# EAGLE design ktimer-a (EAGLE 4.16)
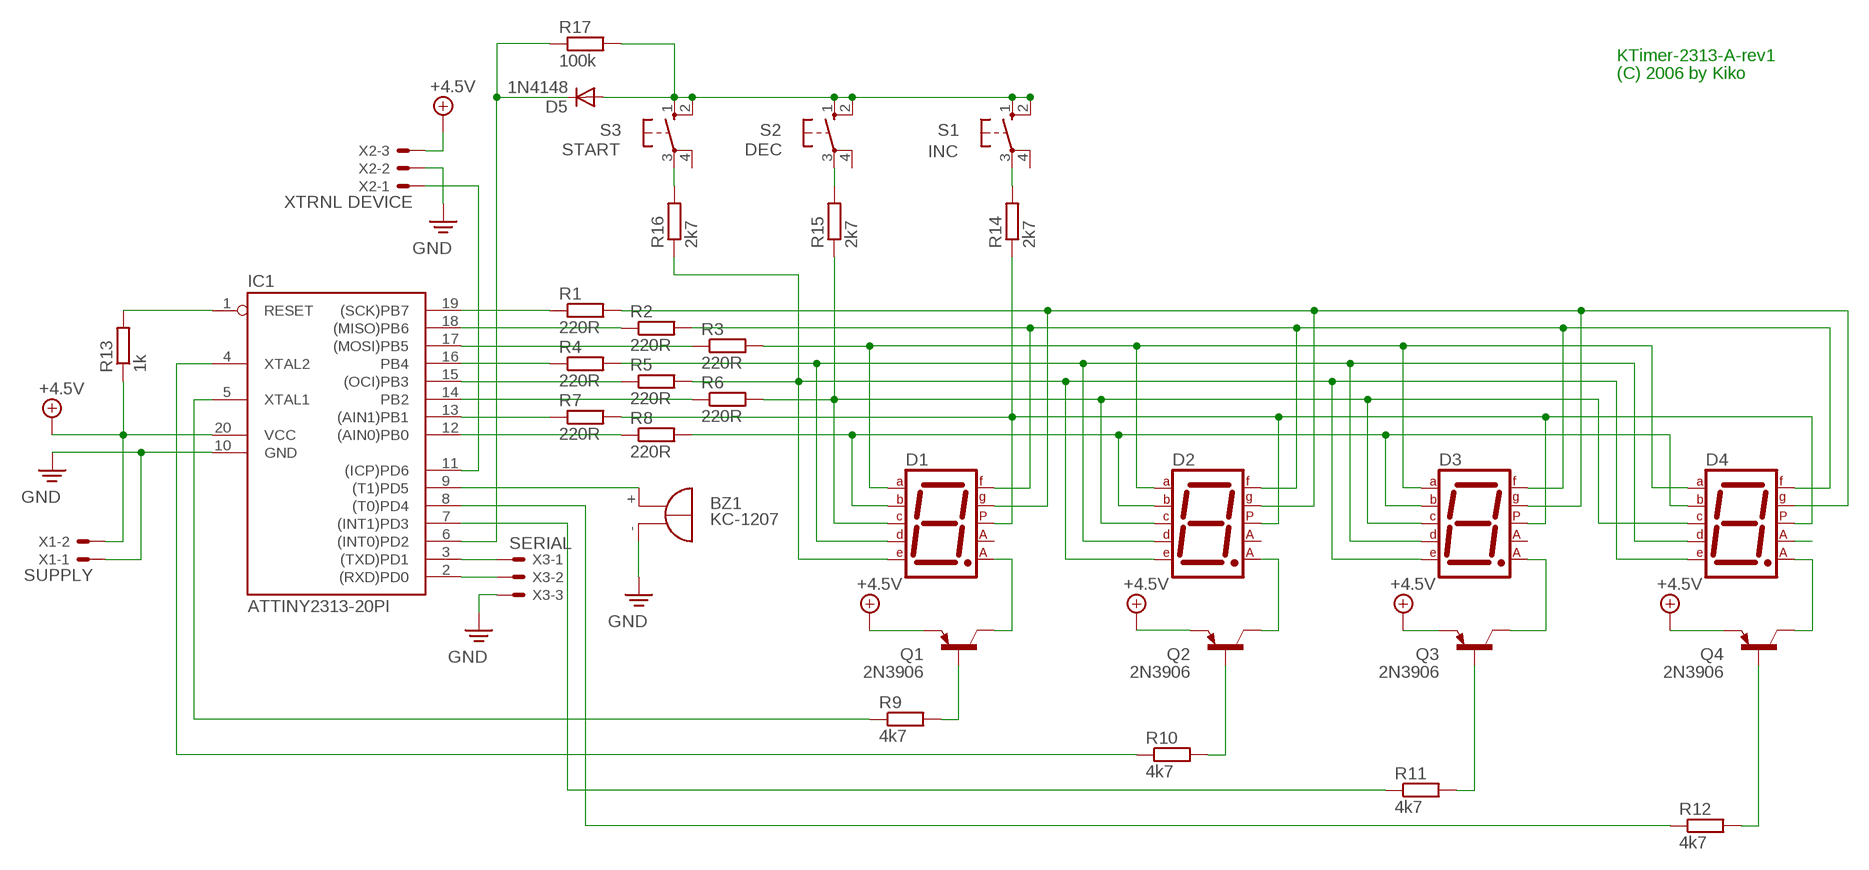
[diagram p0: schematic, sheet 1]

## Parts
BZ1  KC-1207  F/QMBIII  [F/QMBIII]
D1  7SEG-CA  [7SEG-13]
D2  7SEG-CA  [7SEG-13]
D3  7SEG-CA  [7SEG-13]
D4  7SEG-CA  [7SEG-13]
D5  1N4148  BAT81  [DO34-7]
IC1  ATTINY2313-20PI  AT90S2313P  [DIL20]
Q1  2N3906  [TO92]
Q2  2N3906  [TO92]
Q3  2N3906  [TO92]
Q4  2N3906  [TO92]
R1  220R  R-EU_0204/7  [0204/7]
R2  220R  R-EU_0204/7  [0204/7]
R3  220R  R-EU_0204/7  [0204/7]
R4  220R  R-EU_0204/7  [0204/7]
R5  220R  R-EU_0204/7  [0204/7]
R6  220R  R-EU_0204/7  [0204/7]
R7  220R  R-EU_0204/7  [0204/7]
R8  220R  R-EU_0204/7  [0204/7]
R9  4k7  R-EU_0204/7  [0204/7]
R10  4k7  R-EU_0204/7  [0204/7]
R11  4k7  R-EU_0204/7  [0204/7]
R12  4k7  R-EU_0204/7  [0204/7]
R13  1k  R-EU_0204/7  [0204/7]
R14  2k7  R-EU_0204/7  [0204/7]
R15  2k7  R-EU_0204/7  [0204/7]
R16  2k7  R-EU_0204/7  [0204/7]
R17  100k  R-EU_0204/7  [0204/7]
S1  INC  40-XX  [B3F-40XX]
S2  DEC  40-XX  [B3F-40XX]
S3  START  40-XX  [B3F-40XX]
X1  SUPPLY  22-23-2021  [22-23-2021]
X2  XTRNL DEVICE  22-23-2031  [22-23-2031]
X3  SERIAL  22-23-2031  [22-23-2031]

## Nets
+5V: IC1.20(VCC) Q1.3(E) Q2.3(E) Q3.3(E) Q4.3(E) R13.1 X1.2 X2.3 ; supply symbol labelled +4.5V
GND: BZ1.-(+) IC1.10(GND) X1.1 X2.2 X3.3
N$1: D1.10(G) D2.10(G) D3.10(G) D4.10(G) R1.2
N$2: D1.9(F) D2.9(F) D3.9(F) D4.9(F) R2.2
N$3: D1.7(A) D2.7(A) D3.7(A) D4.7(A) R3.2
N$4: D1.2(D) D2.2(D) D3.2(D) D4.2(D) R4.2
N$5: D1.1(E) D2.1(E) D3.1(E) D4.1(E) R5.2 R16.1
N$6: D1.4(C) D2.4(C) D3.4(C) D4.4(C) R6.2 R15.1
N$7: D1.5(DP) D2.5(DP) D3.5(DP) D4.5(DP) R7.2 R14.1
N$8: D1.6(B) D2.6(B) D3.6(B) D4.6(B) R8.2
N$9: IC1.19((SCK)PB7) R1.1
N$10: IC1.18((MISO)PB6) R2.1
N$11: IC1.17((MOSI)PB5) R3.1
N$12: IC1.16(PB4) R4.1
N$13: IC1.15((OCI)PB3) R5.1
N$14: IC1.14(PB2) R6.1
N$15: IC1.13((AIN1)PB1) R7.1
N$16: IC1.12((AIN0)PB0) R8.1
N$17: Q1.2(B) R9.2
N$18: IC1.5(XTAL1) R9.1
N$19: D1.8(CA2) Q1.1(C)
N$20: D2.8(CA2) Q2.1(C)
N$21: D3.8(CA2) Q3.1(C)
N$22: D4.3(CA1)
N$23: Q2.2(B) R10.2
N$24: IC1.4(XTAL2) R10.1
N$25: Q3.2(B) R11.2
N$26: Q4.2(B) R12.2
N$27: IC1.7((INT1)PD3) R11.1
N$28: IC1.8((T0)PD4) R12.1
N$29: IC1.1(RESET) R13.2
N$30: BZ1.+(-) IC1.9((T1)PD5)
N$31: R14.2 S1.3(P)
N$32: R15.2 S2.3(P)
N$33: R16.2 S3.3(P)
N$34: D5.C IC1.6((INT0)PD2) R17.1
N$35: D5.A R17.2 S1.1(S) S1.2(S1) S2.1(S) S2.2(S1) S3.1(S) S3.2(S1)
N$36: D4.8(CA2) Q4.1(C)
N$37: IC1.11((ICP)PD6) X2.1
N$38: IC1.3((TXD)PD1) X3.1
N$39: IC1.2((RXD)PD0) X3.2
Unconnected: D1.3(CA1) D2.3(CA1) D3.3(CA1) S1.4(P1) S2.4(P1) S3.4(P1)

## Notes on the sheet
- KTimer-2313-A-rev1
- (C) 2006 by Kiko

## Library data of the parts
BZ1 = buzzer:F/QMBIII: BUZZER
D1-D4 = special:7SEG-CA: 7-segment DISPLAY single anode, 13 mm
D5 = diode:BAT81: DIODE
IC1 = atmel2:AT90S2313: MICROCONTROLLER 2 Kbytes FLASH 128 bytes SRAM 128 bytes EEPROM UART
Q1-Q4 = transistor-pnp:2N3906: PNP Transistor
R1-R17 = rcl:R-EU_: RESISTOR, European symbol
S1-S3 = switch-omron:40-XX: OMRON SWITCH
X1 = con-molex:22-23-2021: .100" (2.54mm) Center Header - 2 Pin
X2 X3 = con-molex:22-23-2031: .100" (2.54mm) Center Header - 3 Pin

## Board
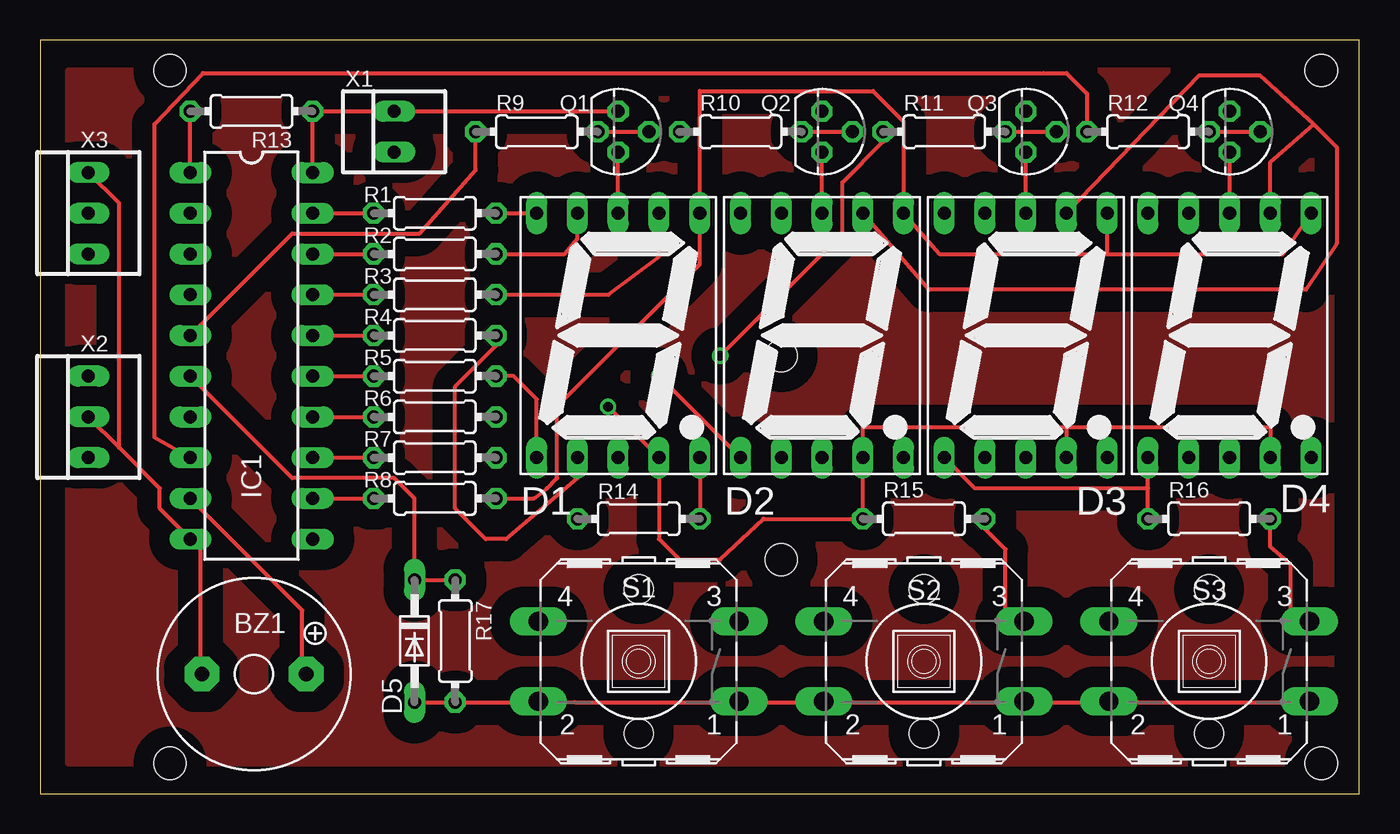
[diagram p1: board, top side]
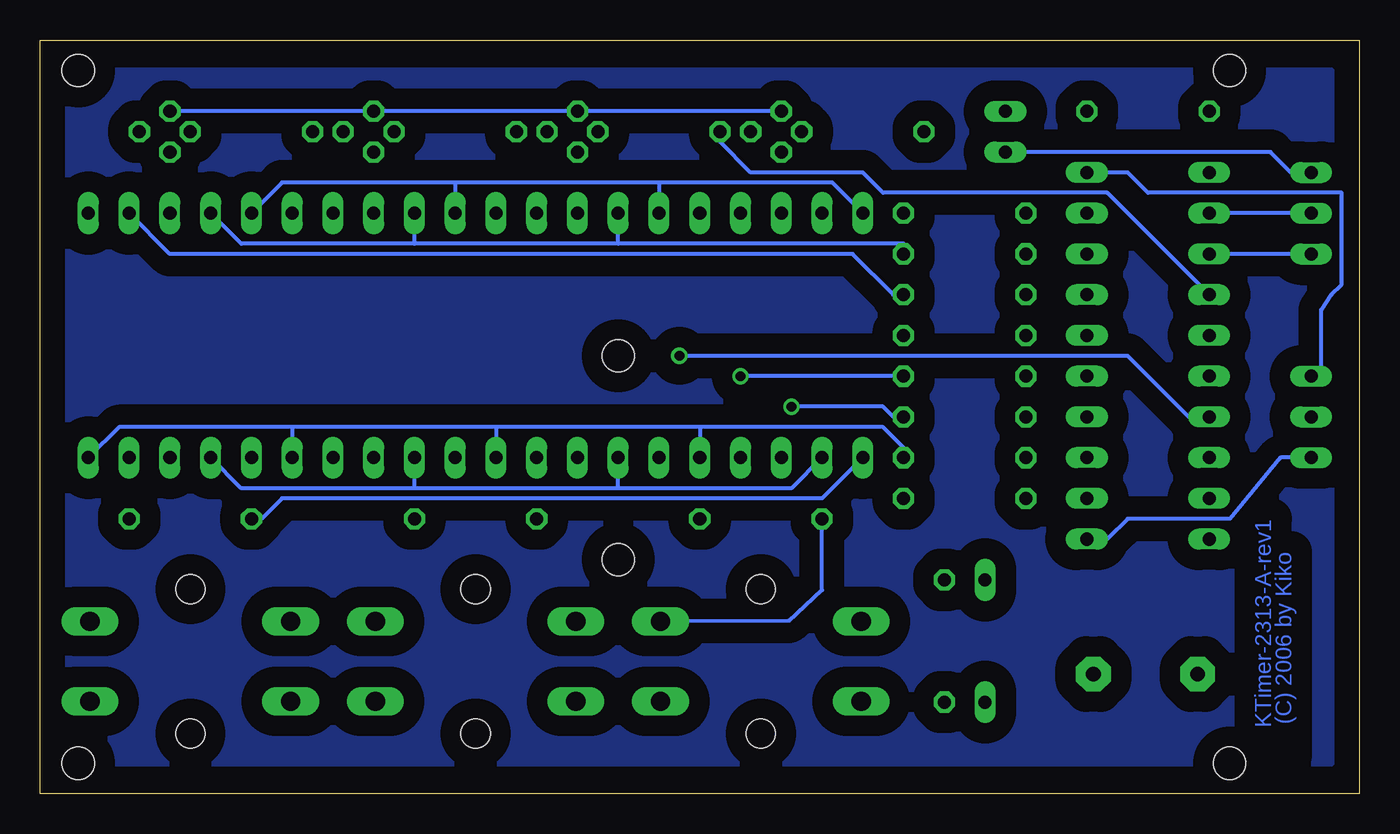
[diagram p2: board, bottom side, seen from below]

Size 82.22 x 46.98 mm. Coordinates in mm from the lower left corner, seen from the top.
Outline: 0,0 82.22,0 82.22,46.98 0,46.98 0,0
Copper layers (1*16): Top 0.035mm / dielectric 1.5mm / Bottom 0.035mm
Design rules "default": minimum track width 10mil, minimum drill 24mil, track to track 8mil, track to pad 8mil, pad to pad 8mil, via to via 8mil, smd to smd 8mil, copper to edge 40mil, drill to drill 8mil, minimum pad ring 10mil, minimum via ring 8mil, stop-mask expansion 4mil, vias tented up to drill 0mil, thermal gap 10mil
Holes 2 mm at 8.09,45.08 8.09,1.9 79.84,1.9 79.84,45.08 46.19,14.6 46.19,27.3

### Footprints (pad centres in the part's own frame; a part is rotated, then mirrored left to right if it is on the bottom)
F/QMBIII = drill 0.914 pad 2.159 octagon: + 3.251,0; - -3.251,0
7SEG-13 = drill 0.813 long: 1 -5.08,-7.62; 2 -2.54,-7.62; 3 0,-7.62; 4 2.54,-7.62; 5 5.08,-7.62; 6 5.08,7.62; 7 2.54,7.62; 8 0,7.62; 9 -2.54,7.62; 10 -5.08,7.62
DO34-7 = drill 0.813 long: A 3.81,0; C -3.81,0
DIL20 = drill 0.813 long: 1 -11.43,-3.81; 2 -8.89,-3.81; 3 -6.35,-3.81; 4 -3.81,-3.81; 5 -1.27,-3.81; 6 1.27,-3.81; 7 3.81,-3.81; 8 6.35,-3.81; 9 8.89,-3.81; 10 11.43,-3.81; 11 11.43,3.81; 12 8.89,3.81; 13 6.35,3.81; 14 3.81,3.81; 15 1.27,3.81; 16 -1.27,3.81; 17 -3.81,3.81; 18 -6.35,3.81; 19 -8.89,3.81; 20 -11.43,3.81
TO92 = drill 0.813 octagon: 1 1.27,0; 2 0,1.905; 3 -1.27,0
0204/7 = drill 0.813 octagon: 1 -3.81,0; 2 3.81,0
B3F-40XX = drill 1.194 long: 1 -6.248,2.489; 2 6.248,2.489; 3 -6.248,-2.489; 4 6.248,-2.489 | hole 1.803: 0,-4.496; 0,4.496
22-23-2021 = drill 0.813 long: 1 -1.27,0; 2 1.27,0
22-23-2031 = drill 0.813 long: 1 -2.54,0; 2 0,0; 3 2.54,0

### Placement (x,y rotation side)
BZ1  13.33,7.46 0 top
D1  36.03,28.57 0 top
D2  48.73,28.57 0 top
D3  61.43,28.57 0 top
D4  74.13,28.57 0 top
D5  23.33,9.52 270 top
IC1  13.17,27.3 270 top
Q1  36.03,41.27 270 top
Q2  48.73,41.27 270 top
Q3  61.43,41.27 270 top
Q4  74.13,41.27 270 top
R1  24.6,36.19 0 top
R2  24.6,33.65 0 top
R3  24.6,31.11 0 top
R4  24.6,28.57 0 top
R5  24.6,26.03 0 top
R6  24.6,23.49 0 top
R7  24.6,20.95 0 top
R8  24.6,18.41 0 top
R9  30.95,41.27 0 top
R10  43.65,41.27 0 top
R11  56.35,41.27 0 top
R12  69.05,41.27 0 top
R13  13.17,42.54 180 top
R14  37.3,17.14 180 top
R15  55.08,17.14 0 top
R16  72.86,17.14 0 top
R17  25.87,9.52 270 top
S1  37.3,8.25 180 top
S2  55.08,8.25 180 top
S3  72.86,8.25 180 top
X1  22.06,41.27 90 top
X2  3.01,23.49 90 top
X3  3.01,36.19 90 top

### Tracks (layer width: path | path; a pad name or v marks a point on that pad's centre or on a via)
+5V
  Top 0.254: IC1.20 R13.1 X1.2 Q1.3
  Bottom 0.254: X2.3 2.38,26.66 2.38,30.16 1.74,31.11 1.11,31.74 1.11,37.46 13.17,37.46 14.44,38.73 IC1.20 | Q1.3 Q2.3 Q3.3 Q4.3
GND
  Top 0.254: 4.92,21.59 7.46,19.04 7.46,17.77 IC1.10 10,15.23 10,8.25 BZ1.- | 4.92,21.59 X2.2 | 4.92,21.59 4.92,36.83 X3.3
  Bottom 0.254: X3.3 4.28,38.73 5.55,40 X1.1
N$1
  Top 0.254: R1.2 D1.10
  Bottom 0.254: 43.65,38.09 56.35,38.09 | 43.65,38.09 D2.10 | 56.35,38.09 D3.10 | 56.35,38.09 67.14,38.09 D4.10 | 43.65,38.09 32.86,38.09 D1.10
N$2
  Top 0.254: R2.2 32.7,33.65 33.49,34.6 D1.9
  Bottom 0.254: 46.19,34.28 28.41,34.28 R2.2 | 46.19,34.28 D2.9 | 46.19,34.28 58.89,34.28 | 58.89,34.28 D3.9 | 58.89,34.28 69.69,34.28 D4.9
N$3
  Top 0.254: R3.2 35.39,31.11 38.57,33.49 D1.7 | 79.37,41.75 76.67,39.37 D4.7 | 79.37,41.75 80.8,40.32 80.8,34.28 78.89,31.43 55.4,31.43 D2.7 | 79.37,41.75 76.03,44.76 72.22,44.76 D3.7
  Bottom 0.254: R3.2 29.04,31.11 31.58,33.65 74.13,33.65 D4.7
N$4
  Top 0.254: R4.2 28.41,27.93 25.87,25.39 25.87,17.77 27.77,15.87 29.04,15.87 33.49,19.68 D1.2
  Bottom 0.254: 46.19,19.04 35.39,19.04 D1.2 | 46.19,19.04 D2.2 | 46.19,19.04 58.89,19.04 | 58.89,19.04 D3.2 | 58.89,19.04 69.69,19.04 D4.2
N$5  (via drill 0.61)
  Top 0.254: 69.05,19.04 58.25,19.04 D3.1 | 69.05,19.04 D4.1 | R16.1 69.05,19.04 | D1.1 30.95,24.6 29.52,26.03 R5.2 | v38.57,26.03 D2.1
  Bottom 0.254: R5.2 v38.57,26.03 | R16.1 68.41,17.14 67.14,18.41 33.49,18.41 D1.1
N$6  (via drill 0.61)
  Top 0.254: 63.97,22.86 76.67,22.86 D4.4 | v35.39,24.12 D1.4 38.57,15.87 39.84,14.6 42.38,14.6 45.08,17.14 R15.1 D2.4 51.27,22.86 63.97,22.86 | 63.97,22.86 D3.4
  Bottom 0.254: v35.39,24.12 29.68,24.12 29.04,23.49 R6.2
N$7
  Top 0.254: D1.5 R14.1
  Bottom 0.254: 41.11,22.86 29.68,22.86 28.41,21.59 R7.2 | 41.11,22.86 D1.5 | 41.11,22.86 53.81,22.86 | 53.81,22.86 D2.5 | 53.81,22.86 66.51,22.86 | 66.51,22.86 D3.5 | 66.51,22.86 77.3,22.86 D4.5
N$8
  Top 0.254: 66.51,33.65 56.03,33.65 D2.6 53.81,41.91 51.91,43.81 41.11,43.81 D1.6 41.11,33.02 32.22,24.12 32.22,19.68 31.58,19.04 30.79,18.41 R8.2 | 66.51,33.65 D3.6 | 66.51,33.65 77.46,33.65 D4.6
N$9
  Top 0.254: IC1.19 R1.1
N$10
  Top 0.254: IC1.18 R2.1
N$11
  Top 0.254: IC1.17 R3.1
N$12
  Top 0.254: IC1.16 R4.1
N$13
  Top 0.254: IC1.15 R5.1
N$14
  Top 0.254: IC1.14 R6.1
N$15
  Top 0.254: IC1.13 R7.1
N$16
  Top 0.254: IC1.12 R8.1
N$17
  Top 0.254: R9.2 Q1.2
N$18
  Top 0.254: IC1.5 15.71,34.92 23.65,34.92 27.14,38.89 R9.1
N$19
  Top 0.254: D1.8 Q1.1
N$20
  Top 0.254: D2.8 Q2.1
N$21
  Top 0.254: D3.8 Q3.1
N$23
  Top 0.254: R10.2 Q2.2
N$24
  Bottom 0.254: IC1.4 15.71,37.46 29.68,37.46 30.95,38.73 37.94,38.73 39.84,40.63 R10.1
N$25
  Top 0.254: R11.2 Q3.2
N$26
  Top 0.254: R12.2 Q4.2
N$27  (via drill 0.61)
  Top 0.254: v42.38,27.3 50,34.92 50,38.09 52.54,40.63 R11.1
  Bottom 0.254: v42.38,27.3 14.44,27.3 10.63,23.49 IC1.7
N$28
  Top 0.254: IC1.8 7.14,22.22 7.14,41.75 10.15,44.92 62.54,44.92 63.97,44.92 65.24,43.65 R12.1
N$29
  Top 0.254: IC1.1 R13.2
N$30
  Top 0.254: IC1.9 16.34,11.42 16.34,8.25 BZ1.+
N$31
  Bottom 0.254: R14.2 33.49,12.7 35.55,10.79 S1.3
N$32
  Top 0.254: R15.2 58.89,16.5 60.16,15.23 60.16,11.42 S2.3
N$33
  Top 0.254: R16.2 76.67,15.39 77.94,14.28 77.94,11.42 S3.3
N$34
  Top 0.254: R17.1 D5.C 23.33,18.41 22.06,19.68 15.71,19.68 IC1.6
N$35
  Top 0.254: S3.1 77.78,5.71 68.41,5.71 S3.2 65.24,5.71 62.7,5.71 S2.1 60.16,5.71 50.64,5.71 S2.2 47.46,5.71 44.92,5.71 S1.1 42.22,5.71 33.33,5.71 S1.2 29.68,5.71 R17.2 D5.A
N$36
  Top 0.254: D4.8 Q4.1
N$37
  Bottom 0.254: X2.1 4.92,20.95 8.09,17.14 14.44,17.14 15.71,15.87 IC1.11
N$38
  Bottom 0.254: X3.1 IC1.3
N$39
  Bottom 0.254: X3.2 IC1.2
N$40
  pour Bottom (isolate 1.27, no thermals): 1.74,45.08 1.74,1.9 80.48,1.9 80.48,45.08
N$41
  pour Top (isolate 1.27, no thermals): 1.74,45.08 1.74,1.9 80.48,1.9 80.48,45.08

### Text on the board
Bottom: KTimer-2313-A-rev1 | (C) 2006 by Kiko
